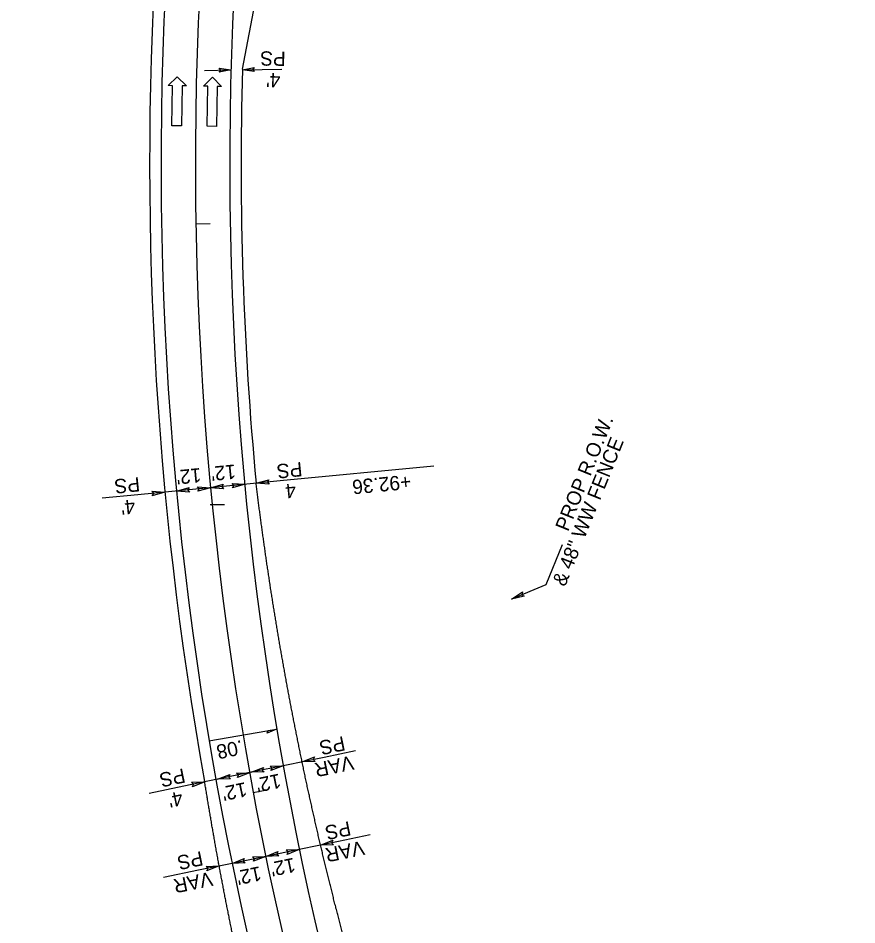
# Model space of a CAD drawing. Extents: x 2389694 to 2405615, y 547005 to 573532.
# Drawn here: x 2395404.2 to 2395697.4, y 556086 to 556402.9 of the extents above; entities that cross this region are included whole.
import ezdxf

# ---------------------------------------------------------------- set-up
doc = ezdxf.new("R2010")
doc.units = 0
for name, color, linetype in [('Old_Level_11', 7, 'Continuous'), ('Prop Dimension', 7, 'Continuous'), ('Prop Dimension Text', 7, 'Continuous'), ('Prop DSN Text', 7, 'Continuous'), ('Prop EOT', 7, 'Continuous'), ('Prop Horizontal Alignment', 7, 'Continuous'), ('Prop Horizontal Alignment Tick Small', 7, 'Continuous'), ('Prop Lane Arrow Through CELL', 7, 'Continuous'), ('Prop Lane Lines', 7, 'Continuous'), ('Prop Super Arrow 1 Lane CELL', 7, 'Continuous'), ('Prop Superelevation Label', 7, 'Continuous')]:
    doc.layers.add(name, color=color, linetype=linetype)

# ---------------------------------------------------------------- blocks, each defined once
blk = doc.blocks.new('TERM')
at = {"layer": 'Old_Level_11'}
blk.add_lwpolyline([(-0.01375, 0.00225), (0, 0), (-0.01375, -0.0025), (-0.012, 0)], close=True, dxfattribs=at)

msp = doc.modelspace()

# ---------------------------------------------------------------- linework, layer by layer
at = {"layer": 'Prop Dimension'}
for p, q in [((2395469.34, 556384.64), (2395478.59, 556384.79)), ((2395482.59, 556384.86), (2395496.39, 556385.08)), ((2395549.48, 556246.37), (2395495.76, 556241.15)), ((2395481.83, 556239.8), (2395469.88, 556238.64)), ((2395495.76, 556241.15), (2395481.83, 556239.8)), ((2395445.99, 556236.32), (2395433.6, 556235.11)), ((2395457.94, 556237.48), (2395445.99, 556236.32)), ((2395469.88, 556238.64), (2395457.94, 556237.48)), ((2395511.12, 556144.56), (2395497.41, 556141.74)), ((2395522.17, 556146.83), (2395511.12, 556144.56)), ((2395497.41, 556141.74), (2395485.65, 556139.32)), ((2395485.65, 556139.32), (2395473.9, 556136.91)), ((2395473.9, 556136.91), (2395462.14, 556134.49)), ((2395462.14, 556134.49), (2395449.95, 556131.98)), ((2395527.24, 556117.44), (2395516.19, 556115.17)), ((2395516.19, 556115.17), (2395502.48, 556112.35)), ((2395490.72, 556109.93), (2395478.97, 556107.51)), ((2395502.48, 556112.35), (2395490.72, 556109.93)), ((2395478.97, 556107.51), (2395467.21, 556105.1)), ((2395467.21, 556105.1), (2395455.02, 556102.59))]:
    msp.add_line(p, q, dxfattribs=at)
for points in [[(2395476, 556238.45), (2395471.44, 556238.79), (2395475.87, 556240.02), (2395475.38, 556239.17)], [(2395478.97, 556240.32), (2395483.52, 556239.99), (2395479.09, 556238.75), (2395479.59, 556239.6)], [(2395491.93, 556240), (2395487.37, 556240.34), (2395491.8, 556241.57), (2395491.3, 556240.72)], [(2395450.97, 556237.58), (2395455.52, 556237.24), (2395451.09, 556236.01), (2395451.59, 556236.86)], [(2395464.05, 556237.29), (2395459.5, 556237.63), (2395463.93, 556238.86), (2395463.43, 556238.01)], [(2395466.89, 556239.12), (2395471.44, 556238.79), (2395467.02, 556237.56), (2395467.51, 556238.41)], [(2395508.02, 556143.13), (2395503.46, 556142.98), (2395507.73, 556144.68), (2395507.33, 556143.78)], [(2395492.27, 556141.47), (2395496.84, 556141.62), (2395492.57, 556139.93), (2395492.97, 556140.83)], [(2395478.46, 556137.05), (2395473.9, 556136.91), (2395478.17, 556138.6), (2395477.77, 556137.7)], [(2395480.52, 556139.06), (2395485.08, 556139.2), (2395480.81, 556137.51), (2395481.21, 556138.41)], [(2395490.22, 556139.47), (2395485.65, 556139.32), (2395489.92, 556141.02), (2395489.52, 556140.12)], [(2395464.84, 556135.83), (2395469.4, 556135.98), (2395465.13, 556134.29), (2395465.53, 556135.19)], [(2395514.48, 556114.03), (2395509.91, 556113.88), (2395514.18, 556115.57), (2395513.78, 556114.67)], [(2395486.16, 556109.78), (2395490.72, 556109.93), (2395486.45, 556108.24), (2395486.85, 556109.14)], [(2395495.29, 556110.08), (2395490.72, 556109.93), (2395494.99, 556111.63), (2395494.59, 556110.73)], [(2395497.91, 556112.2), (2395502.48, 556112.35), (2395498.2, 556110.65), (2395498.61, 556111.55)], [(2395469.91, 556106.44), (2395474.47, 556106.59), (2395470.2, 556104.9), (2395470.6, 556105.79)], [(2395483.53, 556107.66), (2395478.97, 556107.51), (2395483.24, 556109.21), (2395482.84, 556108.31)]]:
    msp.add_lwpolyline(points, close=True, dxfattribs=at)
at = {"layer": 'Prop DSN Text'}
for p, q in [((2395594.34, 556218.88), (2395588.66, 556204.84)), ((2395588.66, 556204.84), (2395576.65, 556199.88))]:
    msp.add_line(p, q, dxfattribs=at)
msp.add_lwpolyline([(2395581.1, 556200.88), (2395576.65, 556199.88), (2395580.52, 556202.35), (2395580.3, 556201.39)], close=True, dxfattribs=at)
at = {"layer": 'Prop EOT'}
for p, q in [((2395482.6, 556385.08), (2395500.32, 556477.13)), ((2395469.37, 556136.19), (2395469.4, 556135.98))]:
    msp.add_line(p, q, dxfattribs=at)
for centre, radius, start, end in [((2398729.82, 555480.32), 3523, 136.54853, 169.40696), ((2398729.82, 555480.32), 3519, 155.66284, 169.40696), ((2396666.13, 556351.64), 1216, 161.88474, 190.20655), ((2396666.13, 556351.64), 1212, 161.88474, 194.38474), ((2396666.13, 556351.64), 1188, 161.88474, 194.38474), ((2396666.13, 556351.64), 1184, 178.38179, 185.39325)]:
    msp.add_arc(centre, radius, start, end, dxfattribs=at)
for points in [[(2395498.01, 556170.77), (2395497.84, 556171.71), (2395497.67, 556172.64), (2395497.5, 556173.58), (2395497.33, 556174.51), (2395497.16, 556175.45), (2395497, 556176.38), (2395496.83, 556177.33), (2395496.66, 556178.26), (2395496.5, 556179.2), (2395496.33, 556180.13), (2395496.17, 556181.07), (2395496.01, 556182), (2395495.84, 556182.95), (2395495.68, 556183.88), (2395495.52, 556184.82), (2395495.36, 556185.76), (2395495.2, 556186.7), (2395495.04, 556187.64), (2395494.89, 556188.57), (2395494.73, 556189.52), (2395494.57, 556190.45), (2395494.42, 556191.39), (2395494.26, 556192.33), (2395494.11, 556193.27), (2395493.95, 556194.21), (2395493.8, 556195.15), (2395493.65, 556196.08), (2395493.5, 556197.03), (2395493.35, 556197.96), (2395493.2, 556198.91), (2395493.05, 556199.84), (2395492.9, 556200.79), (2395492.76, 556201.72), (2395492.61, 556202.67), (2395492.46, 556203.61), (2395492.32, 556204.55), (2395492.17, 556205.49), (2395492.03, 556206.43), (2395491.89, 556207.38), (2395491.74, 556208.31), (2395491.6, 556209.26), (2395491.46, 556210.19), (2395491.32, 556211.14), (2395491.18, 556212.08), (2395491.05, 556213.02), (2395490.91, 556213.96), (2395490.77, 556214.91), (2395490.64, 556215.85), (2395490.5, 556216.79), (2395490.37, 556217.73), (2395490.23, 556218.68), (2395490.1, 556219.62), (2395489.97, 556220.56), (2395489.84, 556221.5), (2395489.7, 556222.45), (2395489.57, 556223.4), (2395489.44, 556224.34), (2395489.32, 556225.28), (2395489.19, 556226.22), (2395489.06, 556227.17), (2395488.94, 556228.11), (2395488.81, 556229.06), (2395488.69, 556230), (2395488.56, 556230.95), (2395488.44, 556231.89), (2395488.32, 556232.84), (2395488.19, 556233.78), (2395488.07, 556234.73), (2395487.95, 556235.67), (2395487.83, 556236.62), (2395487.72, 556237.56), (2395487.6, 556238.51), (2395487.36, 556240.4)], [(2395512.77, 556102.02), (2395512.54, 556102.94), (2395512.31, 556103.86), (2395512.09, 556104.79), (2395511.86, 556105.7), (2395511.64, 556106.63), (2395511.42, 556107.55), (2395511.2, 556108.48), (2395510.98, 556109.4), (2395510.75, 556110.33), (2395510.53, 556111.25), (2395510.31, 556112.17), (2395510.1, 556113.1), (2395509.88, 556114.02), (2395509.66, 556114.95), (2395509.45, 556115.87), (2395509.23, 556116.8), (2395509.02, 556117.72), (2395508.8, 556118.65), (2395508.59, 556119.57), (2395508.38, 556120.5), (2395508.17, 556121.42), (2395507.95, 556122.35), (2395507.74, 556123.28), (2395507.53, 556124.21), (2395507.33, 556125.13), (2395507.12, 556126.06), (2395506.91, 556126.98), (2395506.7, 556127.92), (2395506.5, 556128.85), (2395506.29, 556129.77), (2395506.09, 556130.7), (2395505.89, 556131.63), (2395505.68, 556132.56), (2395505.48, 556133.48), (2395505.28, 556134.42), (2395505.08, 556135.34), (2395504.88, 556136.27), (2395504.68, 556137.2), (2395504.48, 556138.13), (2395504.29, 556139.06), (2395504.09, 556139.99), (2395503.89, 556140.92), (2395503.7, 556141.85), (2395503.5, 556142.78), (2395503.31, 556143.71), (2395503.12, 556144.64), (2395502.92, 556145.57), (2395502.73, 556146.5), (2395502.54, 556147.43), (2395502.35, 556148.37), (2395502.16, 556149.3), (2395501.97, 556150.23), (2395501.79, 556151.16), (2395501.6, 556152.1), (2395501.41, 556153.02), (2395501.23, 556153.96), (2395501.04, 556154.89), (2395500.86, 556155.83), (2395500.67, 556156.75), (2395500.49, 556157.69), (2395500.31, 556158.62), (2395500.13, 556159.56), (2395499.95, 556160.49), (2395499.77, 556161.43), (2395499.59, 556162.35), (2395499.41, 556163.29), (2395499.23, 556164.22), (2395499.06, 556165.16), (2395498.88, 556166.1), (2395498.71, 556167.03), (2395498.53, 556167.97), (2395498.36, 556168.9), (2395498.19, 556169.84), (2395498.01, 556170.77)], [(2395481.93, 556069.55), (2395481.73, 556070.44), (2395481.54, 556071.35), (2395481.35, 556072.24), (2395481.16, 556073.13), (2395480.96, 556074.02), (2395480.77, 556074.92), (2395480.58, 556075.81), (2395480.4, 556076.7), (2395480.21, 556077.6), (2395480.02, 556078.49), (2395479.83, 556079.38), (2395479.65, 556080.28), (2395479.46, 556081.18), (2395479.27, 556082.08), (2395479.09, 556082.97), (2395478.91, 556083.86), (2395478.72, 556084.76), (2395478.54, 556085.65), (2395478.36, 556086.55), (2395478.18, 556087.44), (2395478, 556088.34), (2395477.82, 556089.23), (2395477.64, 556090.13), (2395477.46, 556091.02), (2395477.28, 556091.93), (2395477.1, 556092.82), (2395476.93, 556093.72), (2395476.75, 556094.62), (2395476.58, 556095.51), (2395476.4, 556096.41), (2395476.23, 556097.3), (2395476.06, 556098.2), (2395475.89, 556099.1), (2395475.71, 556099.99), (2395475.54, 556100.89), (2395475.37, 556101.8), (2395475.2, 556102.69), (2395475.03, 556103.59), (2395474.86, 556104.49), (2395474.7, 556105.38), (2395474.53, 556106.28), (2395474.36, 556107.18), (2395474.2, 556108.08), (2395474.03, 556108.97), (2395473.87, 556109.87), (2395473.71, 556110.77), (2395473.54, 556111.68), (2395473.38, 556112.58), (2395473.22, 556113.47), (2395473.06, 556114.37), (2395472.9, 556115.27), (2395472.74, 556116.17), (2395472.58, 556117.07), (2395472.42, 556117.97), (2395472.27, 556118.86), (2395472.11, 556119.76), (2395471.95, 556120.66), (2395471.8, 556121.57), (2395471.64, 556122.47), (2395471.49, 556123.37), (2395471.33, 556124.27), (2395471.18, 556125.17), (2395471.03, 556126.07), (2395470.88, 556126.97), (2395470.73, 556127.87), (2395470.58, 556128.77), (2395470.43, 556129.67), (2395470.28, 556130.57), (2395470.13, 556131.48), (2395469.98, 556132.38), (2395469.84, 556133.28), (2395469.69, 556134.18), (2395469.4, 556135.98)], [(2395531.55, 556034.34), (2395531.27, 556035.25), (2395530.99, 556036.16), (2395530.71, 556037.07), (2395530.43, 556037.98), (2395530.16, 556038.89), (2395529.88, 556039.8), (2395529.6, 556040.7), (2395529.33, 556041.62), (2395529.05, 556042.52), (2395528.78, 556043.44), (2395528.51, 556044.34), (2395528.23, 556045.25), (2395527.96, 556046.16), (2395527.69, 556047.07), (2395527.42, 556047.98), (2395527.15, 556048.89), (2395526.88, 556049.8), (2395526.61, 556050.71), (2395526.35, 556051.62), (2395526.08, 556052.53), (2395525.82, 556053.44), (2395525.55, 556054.36), (2395525.28, 556055.27), (2395525.02, 556056.18), (2395524.76, 556057.09), (2395524.5, 556058), (2395524.23, 556058.92), (2395523.97, 556059.82), (2395523.71, 556060.74), (2395523.45, 556061.65), (2395523.19, 556062.57), (2395522.94, 556063.47), (2395522.68, 556064.39), (2395522.42, 556065.3), (2395522.17, 556066.22), (2395521.91, 556067.13), (2395521.66, 556068.05), (2395521.41, 556068.95), (2395521.15, 556069.87), (2395520.9, 556070.78), (2395520.65, 556071.7), (2395520.4, 556072.61), (2395520.15, 556073.53), (2395519.9, 556074.45), (2395519.65, 556075.36), (2395519.4, 556076.29), (2395519.16, 556077.2), (2395518.91, 556078.12), (2395518.66, 556079.03), (2395518.42, 556079.95), (2395518.18, 556080.86), (2395517.93, 556081.78), (2395517.69, 556082.7), (2395517.45, 556083.62), (2395517.21, 556084.53), (2395516.97, 556085.46), (2395516.73, 556086.37), (2395516.49, 556087.29), (2395516.25, 556088.21), (2395516.01, 556089.13), (2395515.78, 556090.04), (2395515.54, 556090.97), (2395515.3, 556091.89), (2395515.07, 556092.81), (2395514.83, 556093.73), (2395514.6, 556094.65), (2395514.37, 556095.57), (2395514.14, 556096.49), (2395513.91, 556097.41), (2395513.68, 556098.33), (2395513.45, 556099.26), (2395513.22, 556100.17), (2395512.99, 556101.1), (2395512.77, 556102.02)]]:
    msp.add_spline(points, degree=3, dxfattribs=at)
at = {"layer": 'Prop Horizontal Alignment'}
for centre, radius, start, end in [((2398729.82, 555480.32), 3500, 136.54853, 177.15578), ((2396666.13, 556351.64), 1200, 161.88474, 194.38474)]:
    msp.add_arc(centre, radius, start, end, dxfattribs=at)
at = {"layer": 'Prop Horizontal Alignment Tick Small'}
for p, q in [((2395466.3, 556331.05), (2395471.3, 556331.13)), ((2395471.3, 556232.91), (2395476.3, 556232.88)), ((2395486.35, 556132.29), (2395491.26, 556133.2))]:
    msp.add_line(p, q, dxfattribs=at)
at = {"layer": 'Prop Lane Arrow Through CELL'}
for p, q in [((2395456.68, 556379.31), (2395459.83, 556382.41)), ((2395459.83, 556382.41), (2395462.98, 556379.21)), ((2395469, 556379.12), (2395472.15, 556382.22)), ((2395472.15, 556382.22), (2395475.3, 556379.02)), ((2395458.18, 556379.29), (2395456.68, 556379.31)), ((2395457.96, 556365.29), (2395458.18, 556379.29)), ((2395461.48, 556379.24), (2395461.26, 556365.24)), ((2395462.98, 556379.21), (2395461.48, 556379.24)), ((2395470.5, 556379.1), (2395469, 556379.12)), ((2395470.28, 556365.1), (2395470.5, 556379.1)), ((2395473.8, 556379.04), (2395473.58, 556365.05)), ((2395475.3, 556379.02), (2395473.8, 556379.04)), ((2395461.26, 556365.24), (2395457.96, 556365.29)), ((2395473.58, 556365.05), (2395470.28, 556365.1))]:
    msp.add_line(p, q, dxfattribs=at)
at = {"layer": 'Prop Lane Lines'}
for radius in [3547, 3535]:
    msp.add_arc((2398729.82, 555480.32), radius, 136.54853, 169.40696, dxfattribs=at)
at = {"layer": 'Prop Super Arrow 1 Lane CELL'}
msp.add_line((2395470.89, 556150.31), (2395494.53, 556154.45), dxfattribs=at)
msp.add_lwpolyline([(2395494.53, 556154.45), (2395491.22, 556153.06), (2395491.63, 556153.94)], close=True, dxfattribs=at)

# ---------------------------------------------------------------- block references
at = {"layer": 'Prop Dimension'}
for p, xscale, yscale, rotation in [((2395478.59, 556384.79), 300, 300.00000000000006, 0.924629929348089), ((2395482.59, 556384.86), 300.00000000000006, 300, -179.07537007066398)]:
    msp.add_blockref('TERM', p, dxfattribs=dict(at, xscale=xscale, yscale=yscale, rotation=rotation))

# ---------------------------------------------------------------- texts
at = {"layer": 'Prop Dimension Text'}
for s, rotation, p in [('PS', 179.0572, (2395497.77, 556391.19)), ("4'", 179.0572, (2395495.91, 556383.72)), ("12'", 185.5503, (2395480.06, 556246.96)), ('PS', 185.5503, (2395503.28, 556247.81)), ("12'", 185.5503, (2395467.93, 556245.71)), ('+92.36', 185.5503, (2395541.31, 556243.42)), ('PS', 185.5503, (2395446.51, 556242.54)), ('4', 185.5503, (2395501.06, 556240.36)), ("4'", 185.5503, (2395444.86, 556234.77)), ('PS', 191.6199, (2395517.89, 556151.98)), ('VAR', 191.6199, (2395520.89, 556145.24)), ('PS', 191.6199, (2395462, 556140.74)), ("12'", 191.6199, (2395495.47, 556138.92)), ("12'", 191.6199, (2395483.58, 556135.93)), ("4'", 191.6199, (2395461.17, 556132.83)), ('PS', 191.6199, (2395519.9, 556122.3)), ('VAR', 191.6199, (2395524.62, 556115.47)), ('PS', 191.6199, (2395468.22, 556111.82)), ("12'", 191.6199, (2395488.65, 556106.54)), ("12'", 191.6199, (2395500.54, 556109.53)), ('VAR', 191.6199, (2395471.57, 556104.64))]:
    msp.add_text(s, height=5, rotation=rotation, dxfattribs=at).set_placement(p)
at = {"layer": 'Prop DSN Text'}
for s, p in [('PROP R.O.W.', (2395596.41, 556223.24)), ('& 48" WW FENCE', (2395595.38, 556204))]:
    msp.add_text(s, height=5, rotation=68, dxfattribs=at).set_placement(p)
at = {"layer": 'Prop Superelevation Label'}
msp.add_text('.08', height=5, rotation=191.6199, dxfattribs=at).set_placement((2395482.25, 556150.63))

doc.saveas('drawing.dxf')
